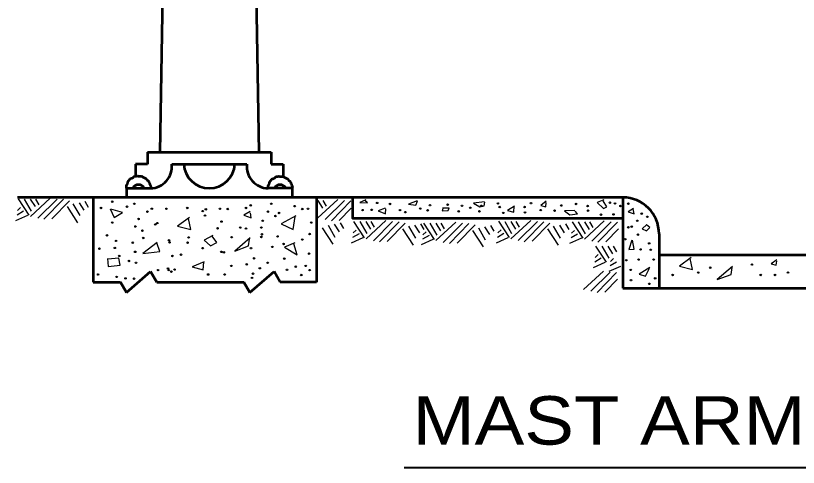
# Model space of a CAD drawing. Extents: x -286 to 394, y -156 to 284.
# Drawn here: x -30.7 to 34, y 111.5 to 148.8 of the extents above; entities that cross this region are included whole.
import ezdxf
from ezdxf.enums import TextEntityAlignment as Align

# ---------------------------------------------------------------- set-up
doc = ezdxf.new("R2010")
doc.units = 0
doc.header["$LTSCALE"] = 0.8
doc.layers.add('1', color=7, linetype='Continuous', lineweight=53)

msp = doc.modelspace()

# ---------------------------------------------------------------- hatches: boundary and pattern name
at = {"layer": '1'}
for points in [[(-22.6645, 133.4098, 1), (-22.7865, 133.4098, 1)], [(-20.8332, 133.2373, 1), (-20.9552, 133.2373, 1)], [(-9.5216, 133.2373, 1), (-9.6436, 133.2373, 1)], [(-0.7752, 133.3102, 1), (-0.8972, 133.3102, 1)], [(0.2837, 133.2254, 1), (0.1617, 133.2254, 1)], [(5.0483, 133.1619, 1), (4.9263, 133.1619, 1)], [(9.1989, 133.2678, 1), (9.0769, 133.2678, 1)], [(11.9306, 133.289, 1), (11.8086, 133.289, 1)], [(15.6577, 133.2254, 1), (15.5357, 133.2254, 1)], [(18.4529, 133.3313, 1), (18.3309, 133.3313, 1)], [(18.8764, 133.2678, 1), (18.7544, 133.2678, 1)], [(19.9803, 133.2483, 1), (19.8583, 133.2483, 1)], [(-23.591, 132.8924, 1), (-23.713, 132.8924, 1)], [(-21.4364, 133.0002, 1), (-21.5584, 133.0002, 1)], [(-19.7558, 132.5907, 1), (-19.8778, 132.5907, 1)], [(-19.3896, 132.8278, 1), (-19.5116, 132.8278, 1)], [(-18.183, 132.8278, 1), (-18.305, 132.8278, 1)], [(-16.4593, 132.8924, 1), (-16.5813, 132.8924, 1)], [(-15.1881, 132.6338, 1), (-15.3101, 132.6338, 1)], [(-14.9296, 132.7847, 1), (-15.0516, 132.7847, 1)], [(-13.7661, 132.8278, 1), (-13.8881, 132.8278, 1)], [(-13.1198, 132.8063, 1), (-13.2417, 132.8063, 1)], [(-11.6115, 132.8924, 1), (-11.7335, 132.8924, 1)], [(-11.2237, 133.108, 1), (-11.3457, 133.108, 1)], [(-9.8017, 132.5907, 1), (-9.9237, 132.5907, 1)], [(-7.5824, 133.0433, 1), (-7.7044, 133.0433, 1)], [(-6.9576, 132.8063, 1), (-7.0796, 132.8063, 1)], [(-6.4836, 132.8278, 1), (-6.6056, 132.8278, 1)], [(-1.9822, 132.7171, 1), (-2.1042, 132.7171, 1)], [(-1.2198, 132.7382, 1), (-1.3418, 132.7382, 1)], [(1.1096, 132.7171, 1), (0.9876, 132.7171, 1)], [(1.5542, 132.5476, 1), (1.4323, 132.5476, 1)], [(2.7825, 132.8442, 1), (2.6605, 132.8442, 1)], [(3.3966, 132.6958, 1), (3.2746, 132.6958, 1)], [(3.5872, 133.1195, 1), (3.4652, 133.1195, 1)], [(5.9589, 132.6112, 1), (5.8369, 132.6112, 1)], [(6.2342, 133.0772, 1), (6.1122, 133.0772, 1)], [(6.9118, 132.9077, 1), (6.7898, 132.9077, 1)], [(7.6742, 132.6112, 1), (7.5522, 132.6112, 1)], [(7.8224, 133.0772, 1), (7.7004, 133.0772, 1)], [(9.3471, 132.9712, 1), (9.2251, 132.9712, 1)], [(11.4012, 132.9712, 1), (11.2793, 132.9712, 1)], [(11.4436, 132.5264, 1), (11.3216, 132.5264, 1)], [(12.7353, 132.7171, 1), (12.6133, 132.7171, 1)], [(13.8788, 132.6747, 1), (13.7568, 132.6747, 1)], [(14.4294, 133.0983, 1), (14.3074, 133.0983, 1)], [(16.6106, 133.056, 1), (16.4886, 133.056, 1)], [(16.6529, 132.6747, 1), (16.5309, 132.6747, 1)], [(19.3212, 133.056, 1), (19.1992, 133.056, 1)], [(-20.4884, 131.9872, 1), (-20.6104, 131.9872, 1)], [(-14.9942, 132.2674, 1), (-15.1162, 132.2674, 1)], [(-9.1768, 132.2243, 1), (-9.2988, 132.2243, 1)], [(-8.8752, 132.4829, 1), (-8.9972, 132.4829, 1)], [(9.6436, 132.484, 1), (9.5216, 132.484, 1)], [(17.7117, 132.3357, 1), (17.5898, 132.3357, 1)], [(18.7493, 132.3569, 1), (18.6273, 132.3569, 1)], [(21.079, 132.4241, 1), (20.957, 132.4241, 1)], [(21.5459, 132.1631, 1), (21.4239, 132.1631, 1)], [(-22.6645, 131.6855, 1), (-22.7865, 131.6855, 1)], [(-20.7469, 131.3622, 1), (-20.8689, 131.3622, 1)], [(-19.1095, 131.5347, 1), (-19.2315, 131.5347, 1)], [(-18.9371, 131.6424, 1), (-19.0591, 131.6424, 1)], [(-13.96, 131.2113, 1), (-14.082, 131.2113, 1)], [(-13.6368, 131.7717, 1), (-13.7588, 131.7717, 1)], [(-12.0855, 131.276, 1), (-12.2075, 131.276, 1)], [(-10.3403, 131.276, 1), (-10.4623, 131.276, 1)], [(-10.2326, 131.8363, 1), (-10.3546, 131.8363, 1)], [(-6.2251, 131.6855, 1), (-6.3471, 131.6855, 1)], [(19.9803, 131.2976, 1), (19.8583, 131.2976, 1)], [(20.255, 131.3526, 1), (20.133, 131.3526, 1)], [(20.7082, 131.8333, 1), (20.5862, 131.8333, 1)], [(-23.0954, 130.6294, 1), (-23.2174, 130.6294, 1)], [(-20.1653, 131.0173, 1), (-20.2872, 131.0173, 1)], [(-11.6115, 131.1898, 1), (-11.7335, 131.1898, 1)], [(-10.2973, 130.7157, 1), (-10.4192, 130.7157, 1)], [(-6.3543, 130.7372, 1), (-6.4763, 130.7372, 1)], [(20.7632, 130.6932, 1), (20.6412, 130.6932, 1)], [(-22.3413, 130.1768, 1), (-22.4633, 130.1768, 1)], [(-20.9624, 130.0259, 1), (-21.0844, 130.0259, 1)], [(-20.1006, 130.4139, 1), (-20.2226, 130.4139, 1)], [(-17.9675, 130.2199, 1), (-18.0895, 130.2199, 1)], [(-17.9244, 130.0475, 1), (-18.0464, 130.0475, 1)], [(-16.4378, 130.0259, 1), (-16.5597, 130.0259, 1)], [(-16.3516, 130.457, 1), (-16.4736, 130.457, 1)], [(-12.7965, 130.4786, 1), (-12.9185, 130.4786, 1)], [(-10.3403, 130.5001, 1), (-10.4623, 130.5001, 1)], [(-9.0045, 130.5432, 1), (-9.1265, 130.5432, 1)], [(-8.5089, 129.9182, 1), (-8.6309, 129.9182, 1)], [(-6.9576, 130.2846, 1), (-7.0796, 130.2846, 1)], [(19.7194, 130.3085, 1), (19.5974, 130.3085, 1)], [(21.697, 129.965, 1), (21.575, 129.965, 1)], [(-23.7203, 129.5302, 1), (-23.8422, 129.5302, 1)], [(-22.4491, 129.5949, 1), (-22.5711, 129.5949, 1)], [(-20.7685, 129.2716, 1), (-20.8905, 129.2716, 1)], [(-15.1881, 129.5733, 1), (-15.3101, 129.5733, 1)], [(-13.6583, 129.2716, 1), (-13.7803, 129.2716, 1)], [(-11.2022, 129.5733, 1), (-11.3242, 129.5733, 1)], [(-9.4354, 129.6811, 1), (-9.5574, 129.6811, 1)], [(20.9828, 129.4705, 1), (20.8608, 129.4705, 1)], [(21.8206, 129.443, 1), (21.6986, 129.443, 1)], [(-22.0828, 128.9267, 1), (-22.2047, 128.9267, 1)], [(-17.6874, 128.9267, 1), (-17.8094, 128.9267, 1)], [(-16.9764, 129.0345, 1), (-17.0984, 129.0345, 1)], [(-13.4429, 129.2285, 1), (-13.5649, 129.2285, 1)], [(-10.9436, 128.7327, 1), (-11.0656, 128.7327, 1)], [(-8.4443, 128.7113, 1), (-8.5662, 128.7113, 1)], [(-6.3974, 129.1207, 1), (-6.5194, 129.1207, 1)], [(20.8181, 128.6325, 1), (20.6961, 128.6325, 1)], [(22.0677, 128.6325, 1), (21.9458, 128.6325, 1)], [(-21.2856, 128.5172, 1), (-21.4076, 128.5172, 1)], [(-20.7038, 128.3664, 1), (-20.8258, 128.3664, 1)], [(-12.8181, 128.1077, 1), (-12.9401, 128.1077, 1)], [(-11.5468, 128.2371, 1), (-11.6688, 128.2371, 1)], [(-9.8232, 128.3664, 1), (-9.9452, 128.3664, 1)], [(-7.4963, 128.0431, 1), (-7.6182, 128.0431, 1)], [(-6.6775, 128.1077, 1), (-6.7995, 128.1077, 1)], [(19.8018, 128.5775, 1), (19.6798, 128.5775, 1)], [(30.1832, 128.2212, 1), (30.0613, 128.2212, 1)], [(-23.828, 127.3965, 1), (-23.95, 127.3965, 1)], [(-18.8725, 127.7629, 1), (-18.9945, 127.7629, 1)], [(-18.0538, 127.8922, 1), (-18.1757, 127.8922, 1)], [(-17.9891, 127.7629, 1), (-18.1111, 127.7629, 1)], [(-17.7736, 127.6336, 1), (-17.8956, 127.6336, 1)], [(-17.5151, 127.806, 1), (-17.6371, 127.806, 1)], [(-14.7357, 127.3965, 1), (-14.8577, 127.3965, 1)], [(-13.3783, 127.3965, 1), (-13.5002, 127.3965, 1)], [(-11.0298, 127.4612, 1), (-11.1517, 127.4612, 1)], [(-10.4696, 127.9137, 1), (-10.5916, 127.9137, 1)], [(-8.2288, 127.7844, 1), (-8.3508, 127.7844, 1)], [(-7.0438, 127.3534, 1), (-7.1657, 127.3534, 1)], [(-6.3543, 127.7629, 1), (-6.4763, 127.7629, 1)], [(20.1726, 127.7807, 1), (20.0506, 127.7807, 1)], [(23.6335, 127.3608, 1), (23.5115, 127.3608, 1)], [(25.7507, 127.5594, 1), (25.6287, 127.5594, 1)], [(26.743, 127.9565, 1), (26.621, 127.9565, 1)], [(30.911, 127.3608, 1), (30.789, 127.3608, 1)], [(32.0941, 127.3608, 1), (31.9721, 127.3608, 1)], [(33.1604, 127.5594, 1), (33.0384, 127.5594, 1)], [(-22.2983, 127.2025, 1), (-22.4202, 127.2025, 1)], [(-21.5657, 127.0733, 1), (-21.6877, 127.0733, 1)], [(-20.8547, 127.0517, 1), (-20.9767, 127.0517, 1)], [(-11.1159, 127.1163, 1), (-11.2379, 127.1163, 1)], [(20.2001, 126.929, 1), (20.0781, 126.929, 1)], [(22.1914, 127.0802, 1), (22.0694, 127.0802, 1)], [(21.7107, 126.6268, 1), (21.5888, 126.6268, 1)]]:
    msp.add_hatch(color=256, dxfattribs=at).paths.add_polyline_path(points)

# ---------------------------------------------------------------- linework, layer by layer
for p, q in [((-16.9518, 243.4995), (-18.8017, 137.5157)), ((-12.2031, 229.2506), (-10.6018, 137.5157)), ((-19.8017, 137.5157), (-9.6018, 137.5157)), ((-19.8017, 137.5157), (-19.8017, 136.5157)), ((-9.6018, 137.5157), (-9.6018, 136.5157)), ((-19.8017, 136.5157), (-20.8017, 136.5157)), ((-20.8017, 136.5157), (-20.8017, 135.5157)), ((-17.8017, 136.5157), (-11.6018, 136.5157)), ((-9.6018, 136.5157), (-8.6018, 136.5157)), ((-8.6018, 136.5157), (-8.6018, 135.4767)), ((-21.5517, 134.5157), (-21.5517, 133.7657)), ((-21.5517, 134.5157), (-19.5517, 134.5157)), ((-7.8518, 134.5157), (-9.8518, 134.5157)), ((-7.8518, 134.5157), (-7.8518, 133.7657)), ((19.4483, 133.7657), (-30.5517, 133.7657)), ((-24.3017, 133.7657), (-24.3017, 126.7657)), ((-5.8518, 133.7657), (-5.8518, 126.7657)), ((19.4483, 133.7657), (19.4483, 126.2657)), ((22.4483, 130.7657), (22.4483, 126.2657)), ((22.4483, 129.0157), (97.4483, 129.0157)), ((-21.5517, 125.8997), (-19.5517, 127.6317)), ((-19.0517, 126.7657), (-19.5517, 127.6317)), ((-11.3518, 125.8997), (-9.3518, 127.6317)), ((-8.8518, 126.7657), (-9.3518, 127.6317)), ((-24.3017, 126.7657), (-22.0517, 126.7657)), ((-21.5517, 125.8997), (-22.0517, 126.7657)), ((-19.0517, 126.7657), (-11.8518, 126.7657)), ((-11.3518, 125.8997), (-11.8518, 126.7657)), ((-5.8518, 126.7657), (-8.8518, 126.7657)), ((19.4483, 126.2657), (97.4483, 126.2657))]:
    msp.add_line(p, q, dxfattribs=at)
at = {"layer": '1', "lineweight": 25}
for p, q in [((-30.5049, 133.64), (-29.626, 132.2909)), ((-29.9897, 133.6248), (-29.4138, 132.6395)), ((-29.4896, 133.6248), (-29.0956, 133.0033)), ((-29.4744, 132.1999), (-27.8378, 133.7158)), ((-29.0652, 133.6248), (-28.7925, 133.1549)), ((-28.8682, 132.0483), (-27.2772, 133.6248)), ((-28.3682, 131.9574), (-26.7467, 133.6097)), ((-27.7166, 131.9877), (-26.2467, 133.4884)), ((-25.9739, 133.2458), (-25.3981, 132.2605)), ((-25.4587, 133.3217), (-25.0647, 132.7002)), ((-24.9737, 133.443), (-24.701, 132.9731)), ((-5.7421, 133.5048), (-5.3481, 132.8833)), ((-5.7269, 132.0799), (-4.0903, 133.5958)), ((-5.3178, 133.5048), (-5.045, 133.0349)), ((-5.1208, 131.9283), (-3.5297, 133.5048)), ((-4.6207, 131.8374), (-2.9992, 133.4897)), ((-30.0502, 132.6243), (-30.5807, 132.306)), ((-30.2927, 132.9276), (-30.5503, 132.685)), ((-26.4588, 133.0185), (-25.5799, 131.6694)), ((-3.9691, 131.8677), (-2.9819, 132.8755)), ((-29.732, 132.2757), (-30.7019, 131.8361)), ((-4.8958, 131.4714), (-4.32, 130.4861)), ((-4.3806, 131.5472), (-3.9866, 130.9257)), ((-3.8957, 131.6686), (-3.6229, 131.1987)), ((-2.786, 131.7812), (-1.9071, 130.4321)), ((-2.2708, 131.766), (-1.6949, 130.7807)), ((-1.7707, 131.766), (-1.3767, 131.1445)), ((-1.7555, 130.3411), (-0.1189, 131.857)), ((-1.3463, 131.766), (-1.0736, 131.2961)), ((-1.1493, 130.1895), (0.4417, 131.766)), ((-0.6492, 130.0986), (0.9722, 131.7508)), ((0.0023, 130.1288), (1.4723, 131.6296)), ((1.745, 131.387), (2.3208, 130.4017)), ((2.2603, 131.4628), (2.6542, 130.8413)), ((2.7452, 131.5842), (3.0179, 131.1142)), ((2.9927, 131.643), (3.8716, 130.2939)), ((3.5079, 131.6278), (4.0838, 130.6425)), ((4.008, 131.6278), (4.402, 131.0063)), ((4.0232, 130.2029), (5.6597, 131.7188)), ((4.4323, 131.6278), (4.7051, 131.1579)), ((4.6293, 130.0513), (6.2204, 131.6278)), ((5.1294, 129.9604), (6.7508, 131.6127)), ((5.781, 129.9907), (7.2509, 131.4914)), ((8.0389, 131.3247), (8.4329, 130.7032)), ((8.5238, 131.446), (8.7966, 130.9761)), ((9.1839, 131.7914), (10.0628, 130.4423)), ((9.6992, 131.7763), (10.275, 130.7909)), ((10.1992, 131.7763), (10.5932, 131.1548)), ((10.2144, 130.3513), (11.851, 131.8672)), ((10.6236, 131.7763), (10.8963, 131.3063)), ((10.8206, 130.1997), (12.4117, 131.7763)), ((11.3207, 130.1088), (12.9421, 131.7611)), ((11.9722, 130.1391), (13.4422, 131.6398)), ((13.7149, 131.3972), (14.2907, 130.4119)), ((14.2302, 131.4731), (14.6242, 130.8516)), ((14.7151, 131.5944), (14.9878, 131.1245)), ((15.2639, 131.7543), (16.1428, 130.4052)), ((15.7792, 131.7392), (16.355, 130.7538)), ((16.2793, 131.7392), (16.6732, 131.1177)), ((16.2944, 130.3142), (17.931, 131.8302)), ((16.7036, 131.7392), (16.9763, 131.2692)), ((16.9006, 130.1627), (18.4917, 131.7392)), ((17.4007, 130.0718), (19.0221, 131.724)), ((-5.3807, 131.2441), (-4.5018, 129.895)), ((-2.3313, 130.7655), (-2.8617, 130.4472)), ((-2.5738, 131.0687), (-2.8314, 130.8262)), ((1.2601, 131.1597), (2.139, 129.8106)), ((3.4473, 130.6273), (2.9169, 130.309)), ((3.2048, 130.9306), (2.9472, 130.688)), ((7.0387, 131.0215), (7.9177, 129.6724)), ((7.5237, 131.2488), (8.0995, 130.2635)), ((9.6386, 130.7757), (9.1082, 130.4574)), ((9.3961, 131.079), (9.1385, 130.8364)), ((13.23, 131.1699), (14.1089, 129.8208)), ((15.7186, 130.7387), (15.1882, 130.4203)), ((15.4761, 131.0419), (15.2185, 130.7993)), ((18.0523, 130.102), (19.0906, 131.1622)), ((-2.0131, 130.4169), (-2.983, 129.9772)), ((3.7656, 130.2788), (2.7957, 129.8391)), ((9.9568, 130.4272), (8.9869, 129.9875)), ((16.0368, 130.3901), (15.0669, 129.9504)), ((17.2102, 129.7518), (18.0892, 128.4027)), ((17.7255, 129.7367), (18.3013, 128.7513)), ((18.2256, 129.7367), (18.6196, 129.1152)), ((18.6499, 129.7367), (18.9227, 129.2668)), ((17.6649, 128.7362), (17.1345, 128.4178)), ((17.4224, 129.0394), (17.1648, 128.7968)), ((18.7015, 128.7241), (18.4439, 128.4815)), ((17.9832, 128.3876), (17.0132, 127.9479)), ((19.2622, 128.0722), (18.2923, 127.6326)), ((18.944, 128.4208), (18.4136, 128.1025)), ((16.2203, 126.1607), (17.8568, 127.6767)), ((16.8264, 126.0092), (18.4175, 127.5857)), ((17.3265, 125.9183), (18.9479, 127.5705)), ((17.9781, 125.9485), (19.0164, 127.0087))]:
    msp.add_line(p, q, dxfattribs=at)
at = {"layer": '1', "lineweight": 40}
msp.add_line((1.3971, 111.4677), (63.2518, 111.4677), dxfattribs=at)
at = {"layer": '1'}
msp.add_lwpolyline([(19.4483, 132.0157), (-2.8518, 132.0157), (-2.8518, 133.7657)], dxfattribs=at)
at = {"layer": '1', "lineweight": 25}
for points in [[(-1.7849, 133.5783), (-2.28, 133.3414), (-1.6342, 133.3199), (-1.8495, 133.5137)], [(2.4775, 133.4707), (1.7456, 133.2122), (2.3483, 133.1261), (2.4991, 133.4491)], [(8.0316, 133.406), (7.1274, 133.2983), (7.6441, 132.9753), (8.0101, 133.0615), (8.0531, 133.3845)], [(13.1336, 133.4491), (12.6815, 133.1046), (13.0905, 132.9969), (13.1336, 133.3414)], [(17.8911, 133.5567), (17.3529, 133.3414), (17.8696, 132.8462), (18.1279, 132.9969), (17.848, 133.4922)], [(-22.8978, 132.8278), (-22.5747, 132.095), (-21.8852, 132.5261), (-22.8332, 132.7848)], [(-11.3277, 132.5907), (-11.8448, 132.289), (-11.2416, 132.0735), (-11.3062, 132.483)], [(-0.1703, 132.8677), (-0.7516, 132.6523), (-0.1488, 132.4155), (-0.1273, 132.8246)], [(4.6087, 132.9322), (4.5227, 132.6523), (5.0177, 132.6738), (5.1254, 132.8677), (4.5872, 132.8893)], [(10.5072, 133.0399), (9.926, 132.6954), (10.4642, 132.5447), (10.4857, 133.0399)], [(15.5016, 132.6738), (14.6405, 132.6523), (15.071, 132.3293), (15.7168, 132.4155), (15.5231, 132.6308)], [(20.3403, 132.8377), (19.9008, 132.5629), (20.3953, 132.4118), (20.3266, 132.8102)], [(-16.3479, 132.095), (-17.3175, 131.3838), (-16.2187, 131.1036), (-16.4341, 132.0304)], [(-7.5572, 132.2459), (-8.7637, 131.5778), (-7.7727, 131.1036), (-7.6003, 132.1813)], [(21.4527, 131.5326), (21.0682, 131.1617), (21.4252, 130.9968), (21.6999, 131.2853), (21.4252, 131.5051)], [(-18.9981, 130.0475), (-20.2046, 129.1207), (-18.7826, 129.2932), (-19.0412, 130.026)], [(-14.4087, 130.6079), (-15.1413, 130.2415), (-14.6027, 129.7673), (-14.0856, 130.0475), (-14.4734, 130.5648)], [(-11.3277, 130.4139), (-12.5989, 129.3363), (-11.457, 129.7673), (-11.3708, 130.3278)], [(-7.6434, 130.0044), (-8.4837, 129.6596), (-7.4495, 129.0346), (-7.7296, 129.9398)], [(20.203, 130.2275), (19.9421, 129.4719), (20.409, 129.4857), (20.2717, 130.2413)], [(-23.1133, 128.7113), (-23.0702, 128.0647), (-22.0791, 128.1724), (-22.1868, 128.7543), (-23.0917, 128.6682)], [(25.0974, 128.7924), (24.1278, 128.0812), (25.2267, 127.801), (25.0113, 128.7278)], [(-15.1198, 128.4526), (-16.1109, 128.0216), (-15.206, 127.7845), (-15.1629, 128.4095)], [(28.5257, 128.055), (27.2546, 126.9773), (28.3965, 127.4084), (28.4827, 127.9688)], [(32.176, 128.6132), (31.7239, 128.2687), (32.1329, 128.1611), (32.176, 128.5056)], [(21.6862, 127.9882), (20.821, 127.4387), (21.3428, 127.2464), (21.6724, 127.9333)]]:
    msp.add_lwpolyline(points, dxfattribs=at)
for centre in [(-22.7255, 133.4098), (-20.8942, 133.2373), (-9.5826, 133.2373), (-0.8362, 133.3102), (0.2227, 133.2254), (4.9873, 133.1619), (9.1379, 133.2678), (11.8696, 133.289), (15.5967, 133.2254), (18.3919, 133.3313), (18.8154, 133.2678), (19.9193, 133.2483), (-23.652, 132.8924), (-21.4974, 133.0002), (-19.8168, 132.5907), (-19.4506, 132.8278), (-18.244, 132.8278), (-16.5203, 132.8924), (-15.2491, 132.6338), (-14.9906, 132.7847), (-13.8271, 132.8278), (-13.1807, 132.8063), (-11.6725, 132.8924), (-11.2847, 133.108), (-9.8627, 132.5907), (-7.6434, 133.0433), (-7.0186, 132.8063), (-6.5446, 132.8278), (-2.0432, 132.7171), (-1.2808, 132.7382), (1.0486, 132.7171), (1.4932, 132.5476), (2.7215, 132.8442), (3.3356, 132.6958), (3.5262, 133.1195), (5.8979, 132.6112), (6.1732, 133.0772), (6.8508, 132.9077), (7.6132, 132.6112), (7.7614, 133.0772), (9.2861, 132.9712), (11.3402, 132.9712), (11.3826, 132.5264), (12.6743, 132.7171), (13.8178, 132.6747), (14.3684, 133.0983), (16.5496, 133.056), (16.5919, 132.6747), (19.2602, 133.056), (-20.5494, 131.9872), (-15.0552, 132.2674), (-9.2378, 132.2243), (-8.9362, 132.4829), (9.5826, 132.484), (17.6507, 132.3357), (18.6883, 132.3569), (21.018, 132.4241), (21.4849, 132.1631), (-22.7255, 131.6855), (-20.8079, 131.3622), (-19.1705, 131.5347), (-18.9981, 131.6424), (-14.021, 131.2113), (-13.6978, 131.7717), (-12.1465, 131.276), (-10.4013, 131.276), (-10.2936, 131.8363), (-6.2861, 131.6855), (19.9193, 131.2976), (20.194, 131.3526), (20.6472, 131.8333), (-23.1564, 130.6294), (-20.2263, 131.0173), (-11.6725, 131.1898), (-10.3582, 130.7157), (-6.4153, 130.7372), (20.7022, 130.6932), (-22.4023, 130.1768), (-21.0234, 130.0259), (-20.1616, 130.4139), (-18.0285, 130.2199), (-17.9854, 130.0475), (-16.4988, 130.0259), (-16.4126, 130.457), (-12.8575, 130.4786), (-10.4013, 130.5001), (-9.0655, 130.5432), (-8.5699, 129.9182), (-7.0186, 130.2846), (19.6584, 130.3085), (21.636, 129.965), (-23.7812, 129.5302), (-22.5101, 129.5949), (-20.8295, 129.2716), (-15.2491, 129.5733), (-13.7193, 129.2716), (-11.2632, 129.5733), (-9.4964, 129.6811), (20.9218, 129.4705), (21.7596, 129.443), (-22.1438, 128.9267), (-17.7484, 128.9267), (-17.0374, 129.0345), (-13.5039, 129.2285), (-11.0046, 128.7327), (-8.5053, 128.7113), (-6.4584, 129.1207), (20.7571, 128.6325), (22.0068, 128.6325), (-21.3466, 128.5172), (-20.7648, 128.3664), (-12.8791, 128.1077), (-11.6078, 128.2371), (-9.8842, 128.3664), (-7.5572, 128.0431), (-6.7385, 128.1077), (19.7408, 128.5775), (30.1222, 128.2212), (-23.889, 127.3965), (-18.9335, 127.7629), (-18.1148, 127.8922), (-18.0501, 127.7629), (-17.8346, 127.6336), (-17.5761, 127.806), (-14.7967, 127.3965), (-13.4392, 127.3965), (-11.0907, 127.4612), (-10.5306, 127.9137), (-8.2898, 127.7844), (-7.1048, 127.3534), (-6.4153, 127.7629), (20.1116, 127.7807), (23.5725, 127.3608), (25.6897, 127.5594), (26.682, 127.9565), (30.85, 127.3608), (32.0331, 127.3608), (33.0994, 127.5594), (-22.3592, 127.2025), (-21.6267, 127.0733), (-20.9157, 127.0517), (-11.1769, 127.1163), (20.1391, 126.929), (22.1304, 127.0802), (21.6498, 126.6268)]:
    msp.add_circle(centre, 0.061, dxfattribs=at)
at = {"layer": '1'}
for centre, radius, start, end in [((-19.5942, 136.3185), 1.8033, 271.35033, 6.27782), ((-14.7017, 136.6181), 2.1024, 182.79209, 357.20791), ((-9.8022, 136.3185), 1.8033, 173.72218, 268.64967), ((-20.5517, 134.2451), 0.5685, 28.42043, 151.57958), ((-8.8518, 134.2451), 0.5685, 28.42043, 151.57958), ((19.4483, 130.7657), 3, 0, 90)]:
    msp.add_arc(centre, radius, start, end, dxfattribs=at)
for points in [[(-21.5517, 134.5157), (-21.5559, 134.6349), (-21.5459, 134.7682), (-21.5192, 134.8149), (-21.4859, 134.865), (-21.4492, 134.9217), (-21.4426, 134.9617), (-21.4326, 135.0217), (-21.4226, 135.0517), (-21.3958, 135.0951), (-21.3692, 135.1484), (-21.3292, 135.1951), (-21.2825, 135.2518), (-21.2625, 135.2952), (-21.2392, 135.3218), (-21.1858, 135.3385), (-21.1125, 135.3552), (-21.0625, 135.3818), (-20.9958, 135.4118), (-20.9625, 135.4519), (-20.9025, 135.4952), (-20.8492, 135.5319), (-20.8017, 135.5157), (-20.6758, 135.5452), (-20.5757, 135.5319), (-20.4991, 135.5219), (-20.4757, 135.5219), (-20.4124, 135.5219), (-20.3857, 135.5252), (-20.3558, 135.5186), (-20.2591, 135.4986), (-20.2191, 135.4586), (-20.1191, 135.4118), (-20.0858, 135.3918), (-20.0024, 135.3652), (-19.9691, 135.3485), (-19.9258, 135.3018), (-19.8724, 135.2652), (-19.8524, 135.2284), (-19.8023, 135.1751), (-19.7657, 135.1384), (-19.739, 135.1151), (-19.7057, 135.0751), (-19.6857, 135.0183), (-19.669, 134.945), (-19.6457, 134.9117), (-19.6057, 134.8216), (-19.579, 134.7749), (-19.549, 134.7016), (-19.5457, 134.6449), (-19.559, 134.5682), (-19.5517, 134.5157)], [(-9.8486, 134.5154), (-9.8517, 134.6031), (-9.8417, 134.7364), (-9.815, 134.7831), (-9.7817, 134.8332), (-9.745, 134.8898), (-9.7383, 134.9298), (-9.7283, 134.9898), (-9.7183, 135.0199), (-9.6916, 135.0632), (-9.6649, 135.1166), (-9.6249, 135.1633), (-9.5782, 135.22), (-9.5582, 135.2633), (-9.5349, 135.29), (-9.4816, 135.3067), (-9.4082, 135.3233), (-9.3582, 135.35), (-9.2916, 135.38), (-9.2583, 135.4201), (-9.1982, 135.4634), (-9.1449, 135.5001), (-9.0974, 135.4838), (-8.9716, 135.5134), (-8.8715, 135.5001), (-8.7948, 135.4901), (-8.7715, 135.4901), (-8.7082, 135.4901), (-8.6815, 135.4934), (-8.6515, 135.4868), (-8.5548, 135.4667), (-8.5148, 135.4267), (-8.4148, 135.38), (-8.3815, 135.36), (-8.2982, 135.3333), (-8.2648, 135.3167), (-8.2215, 135.27), (-8.1682, 135.2333), (-8.1482, 135.1966), (-8.0981, 135.1432), (-8.0614, 135.1066), (-8.0347, 135.0832), (-8.0014, 135.0433), (-7.9814, 134.9865), (-7.9647, 134.9132), (-7.9414, 134.8798), (-7.9014, 134.7897), (-7.8747, 134.7431), (-7.8447, 134.6697), (-7.8414, 134.6131), (-7.8548, 134.5363), (-7.8519, 134.5159)]]:
    msp.add_spline(points, degree=3, dxfattribs=at)

# ---------------------------------------------------------------- texts
at = {"layer": '1', "width": 1.15}
msp.add_text('MAST ARM METHOD', height=4, dxfattribs=at).set_placement((32.505, 113.3451), align=Align.CENTER)

doc.saveas('drawing.dxf')
